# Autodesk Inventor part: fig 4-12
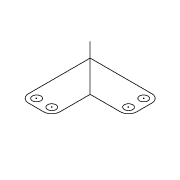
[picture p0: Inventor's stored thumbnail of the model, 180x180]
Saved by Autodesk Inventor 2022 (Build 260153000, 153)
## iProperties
Created: 2005-02
Part Number: fig 4-12
Document SubType Name: Modeling
Designer: CADCIM
Manufacturer: Standard
Standards Organization: Custom
Density: 1 g/cm^3
Material: Generic
Appearance: Default
Author: CADCIM
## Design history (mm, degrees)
sketch "Sketch1"
  geometry: L1 (5.141, 24.979)-(-32.827, 24.979); L2 (-32.827, 24.979)-(-32.827, -12.989); L3 (-27.827, -17.989)-(-18.492, -17.989); L4 (-13.492, -12.989)-(-13.492, 5.644); L5 (-13.492, 5.644)-(5.141, 5.644); L6 (10.141, 10.644)-(10.141, 19.979); L7 (-13.492, 5.644)-(-41.603, 33.755); C1 r 2.58 at (-27.827, -12.989); C2 r 2.58 at (-18.492, -12.989); C3 r 2.58 at (5.141, 10.644); C4 r 2.58 at (5.141, 19.979); A1 r 5 centre (-27.827, -12.989) between (-32.827, -12.989) and (-27.827, -17.989); A2 r 5 centre (-18.492, -12.989) between (-18.492, -17.989) and (-13.492, -12.989); A3 r 5 centre (5.141, 10.644) between (5.141, 5.644) and (10.141, 10.644); A4 r 5 centre (5.141, 19.979) between (10.141, 19.979) and (5.141, 24.979)
  constraints: 14 end point, 8 centre point, 8 point on circle, 8 tangent, 4 equal radius, 4 parallel, 3 perpendicular, 2 coincident, 1 horizontal
